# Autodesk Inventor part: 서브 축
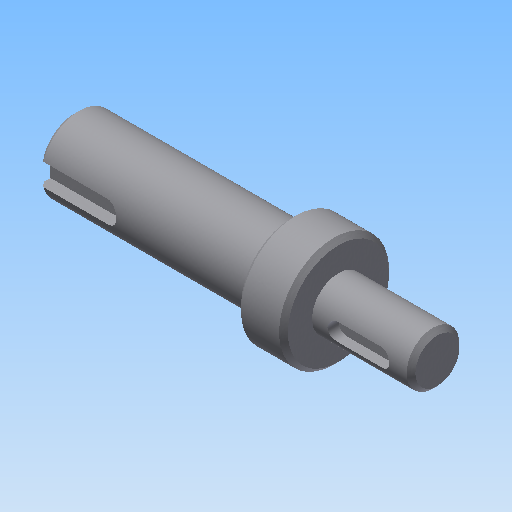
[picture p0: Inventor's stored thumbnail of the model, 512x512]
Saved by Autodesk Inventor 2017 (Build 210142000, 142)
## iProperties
Created: 2014-10
Part Number: 서브 축
Document SubType Name: Modeling
Designer: KYOUNG IL JANG
Density: 1 g/cm^3
Mass: 19.9624 g
Surface Area: 57.7178 cm^2
Volume: 19.9624 cm^3
Material: 강철, 연강
Appearance: 금속-강(스테인리스, 브러시됨)
Author: SeoGD™ [www.esajin.kr]
Revision Number: 1
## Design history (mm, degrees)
sketch "스케치1"
  geometry: L1 (-16.331, 0)-(-98.831, 0); L2 (-16.331, 0)-(-16.331, -6); L3 (-16.331, -6)-(-38.831, -6); L4 (-38.831, -12.5)-(-46.5, -12.5); L5 (-46.5, -8.5)-(-98.831, -8.5); L6 (-98.831, -8.5)-(-98.831, 0); L7 (-46.5, -8.5)-(-46.5, -12.5); L8 (-38.831, -6)-(-38.831, -12.5); L9 (-46.5, 12.249)-(-46.5, -12.249) reference; L10 (-38.831, -17)-(-38.831, 17) reference; 2 further points
  constraints: 17 end point, 4 perpendicular, 2 collinear, 2 parallel, 1 horizontal, 1 midpoint, 1 point on line
  dimensions: "d1" = 12 diameter of L3 L1; "d2" = 25 diameter of L4 L1; "d3" = 17 diameter of L5 L1; "d18" = 22.5 distance of L2.end L3.end; "d20" = 60 distance between parallel lines of L6 L8; "d21" = 7.66872 distance of L4.start L4.end (derived)
revolve "회전1" sketch "스케치1" stored, may be unused: angle "d5" = 90 deg
chamfer "모따기1" distance "d6" = 1; stored, may be unused: second distance "d7" = 2, angle "d8" = 45 deg
node "작업 평면1"
sketch "스케치2"
  geometry: L1 (11.25, 5)-(11.25, -5) reference; L2 (-5.75, -2)-(4.25, -2); L3 (4.25, 2)-(-5.75, 2); A1 r 2 centre (4.25, 0) between (4.25, -2) and (4.25, 2); A2 r 2 centre (-5.75, 0) between (-5.75, 2) and (-5.75, -2); 2 further points
  constraints: 4 end point, 4 point on circle, 4 tangent, 2 centre point, 1 horizontal alignment, 1 midpoint, 1 parallel, 1 perpendicular
  dimensions: "d9" = 4 distance between parallel lines of L2 L3; "d10" = 14 dimension on A1 A2; "d11" = 5 distance edge to line of A1 L1
extrude "돌출1" cut sketch "스케치2" distance "d12" = 2.5; taper "d13" = 0 deg
node "작업 평면2"
sketch "스케치3"
  geometry: L1 (-26.166, -7.5)-(-26.166, 7.5) reference; L2 (-26.166, 2.5)-(-10.666, 2.5); L3 (-10.666, -2.5)-(-26.166, -2.5); A1 r 2.5 centre (-10.666, 0) between (-10.666, -2.5) and (-10.666, 2.5); 2 further points
  constraints: 4 end point, 2 perpendicular, 2 point on circle, 2 point on line, 2 tangent, 1 centre point, 1 horizontal alignment, 1 midpoint
  dimensions: "d14" = 5 distance between parallel lines of L3 L2; "d15" = 18 dimension on A1 L1
extrude "돌출2" cut sketch "스케치3" distance "d16" = 3; taper "d17" = 0 deg
sketch "스케치4"
  geometry: C1 r 12.5 at (0, 0) reference; 1 further point
extrude "돌출3" join sketch "스케치4" distance "d22" = 3; taper "d23" = 0 deg
chamfer "모따기2" distance "d24" = 1; stored, may be unused: second distance "d25" = 2, angle "d26" = 45 deg
node "솔리드1"
node "참조4"
node "참조5"
